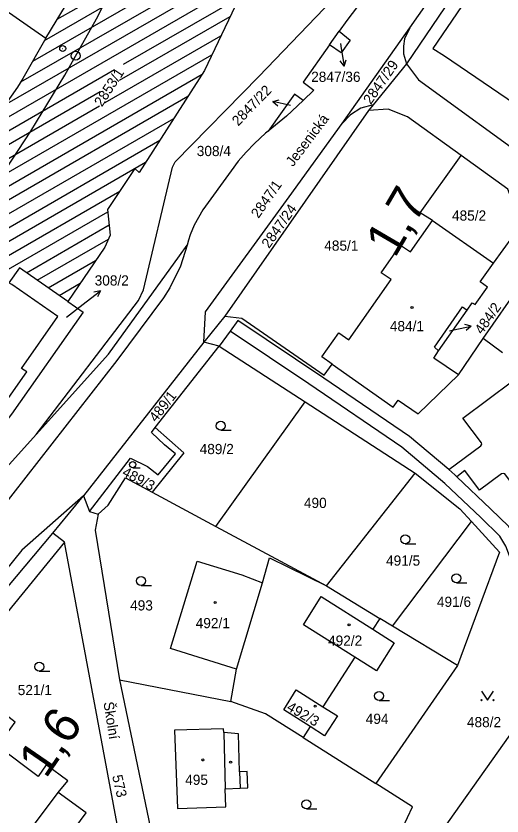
# Model space of a CAD drawing. Extents: x -558500 to -557517, y -1073973 to -1073051.
# Drawn here: x -558087.2 to -558006.2, y -1073436.6 to -1073303.2 of the extents above; entities that cross this region are included whole.
import ezdxf

# ---------------------------------------------------------------- set-up
doc = ezdxf.new("R2010")
doc.units = 0
for name, color, linetype in [('Hranice parcel', 7, 'Continuous'), ('Kolej', 7, 'Continuous'), ('Návěst místo trati', 7, 'Continuous'), ('Parcelní čísla', 7, 'Continuous'), ('Pop  PČ popisy', 7, 'Continuous'), ('Svazek obcí údolí Desné', 7, 'Continuous'), ('Vnitřní kresba', 7, 'Continuous'), ('Značky budov', 7, 'Continuous'), ('Značky kultur', 7, 'Continuous')]:
    doc.layers.add(name, color=color, linetype=linetype)

msp = doc.modelspace()

# ---------------------------------------------------------------- linework, layer by layer
at = {"layer": 'Hranice parcel'}
for p, q in [((-557994.86, -1073270.9), (-558022.09, -1073311.21)), ((-558099.14, -1073295.15), (-558082.18, -1073306.93)), ((-558034.93, -1073308.06), (-558033.31, -1073305.78)), ((-558033.31, -1073305.78), (-558031.49, -1073307.27)), ((-558032.81, -1073321.13), (-558021.55, -1073305.19)), ((-558031.49, -1073307.27), (-558032.97, -1073309.39)), ((-558032.97, -1073309.39), (-558034.93, -1073308.06)), ((-558022.59, -1073309.53), (-558022.09, -1073311.21)), ((-558022.09, -1073311.21), (-558027.65, -1073318.03)), ((-558037.52, -1073315.57), (-558039.34, -1073317.31)), ((-558039.34, -1073317.31), (-558042.1, -1073319.93)), ((-558027.65, -1073318.03), (-558029.72, -1073318.58)), ((-558027.65, -1073318.03), (-558028.41, -1073318.97)), ((-558028.41, -1073318.97), (-558052.39, -1073353.27)), ((-558042.1, -1073319.93), (-558045.13, -1073322.4)), ((-558045.13, -1073322.4), (-558045.59, -1073322.77)), ((-558017.77, -1073337.32), (-558007.59, -1073344.4)), ((-558058.43, -1073340.61), (-558058.64, -1073341.4)), ((-558058.64, -1073341.4), (-558059.76, -1073344.95)), ((-558009.3, -1073357), (-558003.01, -1073347.89)), ((-558055.85, -1073357.6), (-558055.56, -1073352.56)), ((-558016.74, -1073359.04), (-558011.99, -1073352.26)), ((-558052.39, -1073353.27), (-558055.85, -1073357.6)), ((-558051.46, -1073355.75), (-558053.32, -1073358.25)), ((-558055.85, -1073357.6), (-558075.89, -1073383.19)), ((-558053.32, -1073358.25), (-558055.85, -1073357.6)), ((-558013.44, -1073363.06), (-558009.3, -1073357)), ((-558006.08, -1073359.37), (-558009.3, -1073357)), ((-558063.99, -1073371.84), (-558053.32, -1073358.25)), ((-558053.32, -1073358.25), (-558038.99, -1073367.55)), ((-558053.86, -1073388.3), (-558038.99, -1073367.55)), ((-558038.99, -1073367.55), (-558020.67, -1073379.44)), ((-558035.4, -1073398.23), (-558020.67, -1073379.44)), ((-558075.89, -1073383.19), (-558086.19, -1073392.25)), ((-558081, -1073389.4), (-558075.89, -1073383.19)), ((-558075.89, -1073383.19), (-558074.9, -1073385.82)), ((-558064.49, -1073382.58), (-558053.86, -1073388.3)), ((-558074.9, -1073385.82), (-558073.48, -1073386.28)), ((-558024.42, -1073404.91), (-558011.29, -1073387.48)), ((-558053.86, -1073388.3), (-558035.4, -1073398.23)), ((-558116.63, -1073431.7), (-558081, -1073389.4)), ((-558079.07, -1073390.9), (-558081, -1073389.4)), ((-558068.26, -1073448.76), (-558079.07, -1073390.9)), ((-558035.4, -1073398.23), (-558026.52, -1073403.63)), ((-558039.27, -1073404.7), (-558036.29, -1073400)), ((-558036.29, -1073400), (-558027.69, -1073405.45)), ((-558030.69, -1073410.09), (-558039.27, -1073404.7)), ((-558026.52, -1073403.63), (-558027.69, -1073405.45)), ((-558024.42, -1073404.91), (-558026.52, -1073403.63)), ((-558027.69, -1073405.45), (-558024.15, -1073407.69)), ((-558013.61, -1073411.49), (-558024.42, -1073404.91)), ((-558024.15, -1073407.69), (-558027.08, -1073412.36)), ((-558030.69, -1073410.09), (-558036.02, -1073418.35)), ((-558027.08, -1073412.36), (-558030.69, -1073410.09)), ((-558013.61, -1073411.49), (-558027.22, -1073431.17)), ((-558069.9, -1073413.89), (-558063.79, -1073443.12)), ((-558069.9, -1073413.89), (-558051.38, -1073417.49)), ((-558042.56, -1073418.87), (-558040.48, -1073415.56)), ((-558040.48, -1073415.56), (-558036.02, -1073418.35)), ((-558038.16, -1073421.67), (-558042.56, -1073418.87)), ((-558036.02, -1073418.35), (-558033.6, -1073419.86)), ((-558033.6, -1073419.86), (-558035.74, -1073423.21)), ((-558038.16, -1073421.67), (-558039.34, -1073423.5)), ((-558035.74, -1073423.21), (-558038.16, -1073421.67)), ((-558039.34, -1073423.5), (-558027.22, -1073431.17))]:
    msp.add_line(p, q, dxfattribs=at)
for points in [[(-557998.11, -1073217.81), (-557996.7, -1073222.28), (-557998.38, -1073242.39), (-558002.78, -1073257.43), (-558008.62, -1073269.37), (-558024.06, -1073293.44), (-558032.02, -1073303.96), (-558033.31, -1073305.78)], [(-558021.55, -1073305.19), (-558007.79, -1073285.56), (-557998.91, -1073272.25), (-557998.29, -1073271.45), (-557997.41, -1073270.82), (-557995.96, -1073270.7)], [(-557992.18, -1073271.14), (-558017.7, -1073308.66), (-558015.75, -1073309.85), (-558004.08, -1073317.8), (-557996.67, -1073322.48), (-557993.43, -1073325.31), (-557988.49, -1073331.84)], [(-558021.55, -1073305.19), (-558022.41, -1073307.04), (-558022.62, -1073308.24), (-558022.59, -1073309.53)], [(-558034.93, -1073308.06), (-558039.34, -1073314.26), (-558037.52, -1073315.57)], [(-558022.09, -1073311.21), (-558020.08, -1073313.87), (-558000.41, -1073328.2), (-557993.92, -1073334.5), (-557986.04, -1073343.93), (-557967.1, -1073369.2), (-557918.24, -1073434.51), (-557914.64, -1073436.24), (-557909.55, -1073436.22), (-557905.05, -1073434.1), (-557902.57, -1073430.65), (-557891.22, -1073414.37), (-557877.97, -1073395.43)], [(-558039.34, -1073317.31), (-558040.78, -1073316.28), (-558045.13, -1073322.4)], [(-558029.72, -1073318.58), (-558031.41, -1073319.68), (-558032.81, -1073321.13)], [(-558012.98, -1073326.49), (-558021.93, -1073320.01), (-558025.13, -1073318.78), (-558028.41, -1073318.97)], [(-558055.56, -1073352.56), (-558041.67, -1073333.36), (-558032.81, -1073321.13)], [(-558045.59, -1073322.77), (-558047.44, -1073324.48), (-558048.82, -1073325.91), (-558050.13, -1073327.44), (-558051.32, -1073329.04), (-558056.02, -1073335.51), (-558057.5, -1073338.08), (-558058.16, -1073339.69), (-558058.43, -1073340.61)], [(-558017.77, -1073337.32), (-558019.82, -1073336.05), (-558012.98, -1073326.49)], [(-558007.59, -1073344.4), (-558004.4, -1073339.98), (-558003.75, -1073335.95), (-558005.22, -1073332.12), (-558012.98, -1073326.49)], [(-558034.47, -1073361.24), (-558036.19, -1073360.05), (-558033.38, -1073356.04), (-558031.73, -1073357.2), (-558024.67, -1073347.17), (-558026.34, -1073346.01), (-558023.11, -1073341.4), (-558021.44, -1073342.56), (-558017.77, -1073337.32)], [(-558083.8, -1073372.96), (-558071.77, -1073359.59), (-558059.92, -1073343.2), (-558058.64, -1073341.4)], [(-558011.99, -1073352.26), (-558011.14, -1073351.05), (-558010.65, -1073351.33), (-558008.6, -1073348.45), (-558009.82, -1073347.53), (-558007.59, -1073344.4)], [(-558059.76, -1073344.95), (-558061.55, -1073348.53), (-558062.6, -1073350.23), (-558070.37, -1073360.66), (-558089.91, -1073385.65), (-558114.04, -1073415.6), (-558119.93, -1073422.75), (-558120.74, -1073423.38), (-558121.71, -1073423.79), (-558122.74, -1073423.86)], [(-558100.88, -1073366.68), (-558093.95, -1073371.49), (-558091.09, -1073367.38), (-558089.54, -1073368.47), (-558085.38, -1073362.53), (-558086.24, -1073361.96), (-558080.2, -1073353.3), (-558087.87, -1073347.97), (-558088.33, -1073347.7)], [(-558016.74, -1073359.04), (-558017.42, -1073358.44), (-558012.76, -1073351.73), (-558011.99, -1073352.26)], [(-558052.39, -1073353.27), (-558049.55, -1073353.62), (-558035.82, -1073363.11), (-558034.47, -1073361.24)], [(-558015.07, -1073378.83), (-558021.62, -1073373.3), (-558035.88, -1073363.58), (-558050.18, -1073353.97), (-558051.46, -1073355.75)], [(-557997.16, -1073446.28), (-557996.18, -1073446.14), (-557992.37, -1073440.37), (-557993.13, -1073429.99), (-557993.58, -1073428.02), (-558004.25, -1073395), (-558005.55, -1073391.58), (-558006.57, -1073389.94), (-558009.69, -1073386.81), (-558015.69, -1073381.13), (-558022.86, -1073375.1), (-558038.38, -1073364.54), (-558051.46, -1073355.75)], [(-558015.07, -1073378.83), (-558009.7, -1073374.87), (-558009.55, -1073374.62), (-558009.63, -1073374.36), (-558012.72, -1073370.26), (-557996.07, -1073357.8), (-557992.97, -1073361.92), (-557992.74, -1073362.04), (-557992.48, -1073361.98), (-557989.05, -1073359.38), (-557985.61, -1073364.04), (-557988.36, -1073366.15), (-557988.52, -1073366.38), (-557988.48, -1073366.66), (-557985.4, -1073370.76), (-558002.63, -1073383.68), (-558005.71, -1073379.56), (-558005.98, -1073379.48), (-558006.26, -1073379.51), (-558009.96, -1073382.24), (-558012.37, -1073378.99), (-558013.71, -1073380.01)], [(-558013.44, -1073363.06), (-558017.55, -1073360.24), (-558016.74, -1073359.04)], [(-558034.47, -1073361.24), (-558024.32, -1073368.43), (-558023.47, -1073367.24), (-558020.17, -1073369.56), (-558013.44, -1073363.06)], [(-558074.9, -1073385.82), (-558068.06, -1073376.95), (-558065.25, -1073378.32), (-558063.46, -1073379.72), (-558060.6, -1073376.18), (-558062.42, -1073374.7), (-558064.61, -1073372.63), (-558063.99, -1073371.84)], [(-558063.99, -1073371.84), (-558059.19, -1073376.03), (-558064.49, -1073382.58)], [(-558020.67, -1073379.44), (-558013.21, -1073385.39), (-558011.29, -1073387.48)], [(-558013.71, -1073380.01), (-558014.05, -1073379.69), (-558015.07, -1073378.83)], [(-558073.48, -1073386.28), (-558071.82, -1073384.76), (-558068.89, -1073380.22), (-558064.49, -1073382.58)], [(-557986.61, -1073406.29), (-557987.5, -1073406.44), (-558001.47, -1073396.48), (-558002.38, -1073393.7), (-558003.7, -1073390.42), (-558005.05, -1073388.34), (-558008.08, -1073385.35), (-558013.71, -1073380.01)], [(-558073.48, -1073386.28), (-558073.96, -1073388.93), (-558069.9, -1073413.89)], [(-558011.29, -1073387.48), (-558006.6, -1073392.58), (-558013.61, -1073411.49)], [(-558079.07, -1073390.9), (-558096.99, -1073412.88), (-558100.23, -1073417.28)], [(-558086.19, -1073392.25), (-558100.56, -1073410.01), (-558117.51, -1073431.08), (-558131.78, -1073449.27), (-558138.48, -1073457.68), (-558143.38, -1073464.02), (-558146.99, -1073468.89), (-558150.46, -1073473.83), (-558152.02, -1073476.41), (-558154.26, -1073480.97), (-558156.46, -1073486.6), (-558158.91, -1073494.31), (-558160.3, -1073500.48), (-558162.16, -1073510.4), (-558165.76, -1073536.46), (-558169.94, -1073565.43), (-558173.74, -1073591.61), (-558177.66, -1073620.33), (-558178.51, -1073631.87), (-558179.02, -1073643), (-558179.24, -1073655.12), (-558179.45, -1073666.94), (-558179.49, -1073675.4)], [(-558051.38, -1073417.49), (-558050.42, -1073412.09), (-558061.44, -1073408.67), (-558056.95, -1073394.08), (-558049.56, -1073396.36), (-558046.09, -1073397.7), (-558044.91, -1073393.54), (-558035.4, -1073398.23)], [(-558079.09, -1073440.91), (-558075.49, -1073436.06), (-558080.13, -1073432.64), (-558078.53, -1073430.7), (-558082.12, -1073428.01), (-558083.47, -1073429.99), (-558090.26, -1073424.91), (-558087.3, -1073420.92), (-558091.08, -1073418.03), (-558093.98, -1073421.97), (-558100.23, -1073417.28)], [(-558039.34, -1073423.5), (-558045.61, -1073419.54), (-558051.38, -1073417.49)], [(-558049.8, -1073431.93), (-558048.54, -1073431.88), (-558048.64, -1073429.15), (-558049.91, -1073429.2), (-558050.08, -1073422.86), (-558052.56, -1073422.66), (-558052.57, -1073422.02), (-558060.76, -1073422.24), (-558060.26, -1073435.32), (-558052.21, -1073435.02), (-558052.32, -1073432.02), (-558049.8, -1073431.93)], [(-558023.22, -1073448.98), (-558004.82, -1073423.06), (-557993.94, -1073430.83), (-558002.36, -1073442.69), (-558001.05, -1073443.62)], [(-558024.27, -1073448.53), (-558022.77, -1073438.58), (-558021.1, -1073435.02), (-558027.22, -1073431.17)]]:
    msp.add_lwpolyline(points, dxfattribs=at)
at = {"layer": 'Kolej'}
msp.add_lwpolyline([(-558164.78, -1073439.38), (-558155.66, -1073426.13), (-558147.22, -1073413.85), (-558143.69, -1073408.73), (-558141.06, -1073404.9), (-558137.3, -1073399.44), (-558134.57, -1073395.46), (-558131.72, -1073391.31), (-558124.89, -1073381.38), (-558115.4, -1073367.56), (-558106.18, -1073354.16), (-558097.49, -1073341.51), (-558095.26, -1073338.27), (-558090.95, -1073331.93), (-558084.7, -1073322.4), (-558079.04, -1073313.09), (-558073.77, -1073303.7), (-558068.68, -1073293.77)], dxfattribs=at)
at = {"layer": 'Návěst místo trati'}
msp.add_line((-558079.43, -1073308.65), (-558079.33, -1073308.65), dxfattribs=at)
for centre, radius in [((-558079.38, -1073308.65), 0.5), ((-558077.22, -1073309.86), 0.75)]:
    msp.add_circle(centre, radius, dxfattribs=at)
at = {"layer": 'Pop  PČ popisy'}
for p, q in [((-558033.09, -1073307.84), (-558032.96, -1073308.65)), ((-558032.96, -1073308.65), (-558032.49, -1073311.61)), ((-558032.49, -1073311.61), (-558033.14, -1073310.7)), ((-558032.49, -1073311.61), (-558032.15, -1073310.55)), ((-558044.37, -1073317.47), (-558043.29, -1073317.2)), ((-558041.45, -1073318.14), (-558044.37, -1073317.47)), ((-558044.37, -1073317.47), (-558043.51, -1073318.18)), ((-558075.47, -1073350.88), (-558073.1, -1073349.03)), ((-558073.1, -1073349.03), (-558074.2, -1073349.25)), ((-558073.1, -1073349.03), (-558073.59, -1073350.04)), ((-558078.72, -1073353.4), (-558075.47, -1073350.88)), ((-558014.95, -1073355.7), (-558014.23, -1073355.56)), ((-558014.23, -1073355.56), (-558011.3, -1073354.94)), ((-558011.3, -1073354.94), (-558012.38, -1073354.65)), ((-558011.3, -1073354.94), (-558012.17, -1073355.63))]:
    msp.add_line(p, q, dxfattribs=at)
at = {"layer": 'Svazek obcí údolí Desné'}
for p, q in [((-558080.29, -1073303.78), (-558043.65, -1073282.63)), ((-558082.4, -1073307.31), (-558044.27, -1073285.3)), ((-558084.38, -1073310.76), (-558044.89, -1073287.97)), ((-558086.37, -1073314.22), (-558045.51, -1073290.64)), ((-558089.02, -1073318.06), (-558046.97, -1073293.79)), ((-558091.87, -1073322.02), (-558048.48, -1073296.97)), ((-558069.24, -1073311.26), (-558049.99, -1073300.15)), ((-558069.89, -1073313.95), (-558051.5, -1073303.33)), ((-558072.29, -1073317.64), (-558053.01, -1073306.51)), ((-558103.16, -1073337.77), (-558054.52, -1073309.69)), ((-558094.72, -1073325.97), (-558070.74, -1073312.13)), ((-558105.92, -1073341.68), (-558056.17, -1073312.95)), ((-558108.69, -1073345.58), (-558058.52, -1073316.62)), ((-558097.57, -1073329.93), (-558073.14, -1073315.82)), ((-558100.39, -1073333.87), (-558073.26, -1073318.21)), ((-558111.45, -1073349.49), (-558060.87, -1073320.29)), ((-558114.21, -1073353.39), (-558063.22, -1073323.95)), ((-558116.98, -1073357.3), (-558065.57, -1073327.62)), ((-558119.74, -1073361.21), (-558069.87, -1073332.41)), ((-558122.51, -1073365.11), (-558071.87, -1073335.87)), ((-558085.42, -1073346.01), (-558071.63, -1073338.05)), ((-558083.61, -1073347.27), (-558071.76, -1073340.43)), ((-558081.79, -1073348.53), (-558073.89, -1073343.97)), ((-558086.59, -1073345.2), (-558088.33, -1073347.7)), ((-558078.52, -1073350.81), (-558086.59, -1073345.2)), ((-558079.98, -1073349.8), (-558076.46, -1073347.76)), ((-558083.8, -1073372.96), (-558066.74, -1073350.64)), ((-558092.4, -1073382.52), (-558083.8, -1073372.96))]:
    msp.add_line(p, q, dxfattribs=at)
for points in [[(-558082.18, -1073306.93), (-558073.77, -1073292.96), (-558066.53, -1073276.76), (-558060.05, -1073257.85), (-558056.4, -1073244.89), (-558045.6, -1073201.5), (-558043.14, -1073189.96)], [(-558025.67, -1073189.86), (-558032.09, -1073212.63), (-558035.15, -1073249.33), (-558039.97, -1073265.01), (-558041.24, -1073272.26), (-558045.55, -1073290.79), (-558055.77, -1073312.33), (-558066.64, -1073329.29), (-558067.37, -1073328.67), (-558071.91, -1073335.47), (-558071.45, -1073339.78), (-558072.38, -1073341.74), (-558078.52, -1073350.81)], [(-558066.74, -1073350.64), (-558065.9, -1073348.86), (-558061.08, -1073328.44), (-558060.65, -1073327.54), (-558046.7, -1073313.29), (-558030.4, -1073296.27), (-558015.33, -1073274.48), (-558010.02, -1073266.4), (-558006.82, -1073259.79), (-558003.58, -1073251.39), (-558001.93, -1073245.63), (-558000.3, -1073233.47), (-558000.14, -1073230.76), (-558000.21, -1073228.76), (-558000.67, -1073225.31), (-558001.93, -1073222.03), (-558003.18, -1073219.55), (-558003.41, -1073218.32), (-558003.28, -1073217.31), (-558002.8, -1073216.38), (-558000.9, -1073214.81), (-557999.34, -1073213.91), (-558005.3, -1073194.99), (-558007.3, -1073189.81)], [(-558082.18, -1073306.93), (-558086.02, -1073313.63), (-558086.89, -1073315.11), (-558091.21, -1073321.1)], [(-558078.52, -1073350.81), (-558075.97, -1073352.58), (-558087.9, -1073369.62), (-558096.11, -1073380.17)]]:
    msp.add_lwpolyline(points, dxfattribs=at)
at = {"layer": 'Vnitřní kresba'}
for p, q in [((-558050.42, -1073412.09), (-558046.09, -1073397.7)), ((-558052.56, -1073422.66), (-558052.32, -1073432.02)), ((-558049.91, -1073429.2), (-558049.8, -1073431.93)), ((-558086.64, -1073441.31), (-558080.13, -1073432.64))]:
    msp.add_line(p, q, dxfattribs=at)
at = {"layer": 'Značky budov'}
for centre in [(-558021.18, -1073351.82), (-558053.98, -1073400.98), (-558031.67, -1073404.71), (-558037.33, -1073418.27), (-558056.04, -1073427.22), (-558051.4, -1073427.58)]:
    msp.add_circle(centre, 0.175, dxfattribs=at)
at = {"layer": 'Značky kultur'}
for p, q in [((-558053.04, -1073372.28), (-558051.29, -1073372.28)), ((-558067.72, -1073378.52), (-558066.5, -1073378.52)), ((-558022.31, -1073391.2), (-558020.56, -1073391.2)), ((-558066.32, -1073398.13), (-558064.57, -1073398.13)), ((-558013.78, -1073397.68), (-558012.03, -1073397.68)), ((-558083.29, -1073412.44), (-558081.54, -1073412.44)), ((-558026.66, -1073417.3), (-558024.91, -1073417.3)), ((-558038.77, -1073435.36), (-558037.02, -1073435.36))]:
    msp.add_line(p, q, dxfattribs=at)
msp.add_lwpolyline([(-558009.6, -1073415.75), (-558008.6, -1073417.25), (-558007.6, -1073415.75)], dxfattribs=at)
for centre, radius in [((-558053.04, -1073371.53), 0.75), ((-558067.72, -1073378), 0.525), ((-558022.31, -1073390.45), 0.75), ((-558066.32, -1073397.38), 0.75), ((-558013.78, -1073396.93), 0.75), ((-558083.29, -1073411.69), 0.75), ((-558026.66, -1073416.55), 0.75), ((-558009.6, -1073417.25), 0.1), ((-558007.6, -1073417.25), 0.1), ((-558038.77, -1073434.61), 0.75)]:
    msp.add_circle(centre, radius, dxfattribs=at)

# ---------------------------------------------------------------- texts
at = {"layer": 'Návěst místo trati'}
for s, rotation, p in [('1,7', 59.7051, (-558024.05, -1073343.72)), ('1,6', 55.5139, (-558082.19, -1073430.47))]:
    msp.add_text(s, height=6, rotation=rotation, dxfattribs=at).set_placement(p)
at = {"layer": 'Parcelní čísla'}
for s, rotation, p in [('2847/29', 55, (-558028.06, -1073318.09)), ('2853/1', 57, (-558072.84, -1073318.48)), ('2847/22', 46, (-558050.14, -1073321.67)), ('2847/1', 55, (-558046.76, -1073337.06)), ('2847/24', 55, (-558045, -1073342.08)), ('484/2', 55, (-558009.5, -1073356.42)), ('489/1', 52, (-558063.81, -1073371.04)), ('489/3', 332, (-558069.62, -1073379.77)), ('492/3', 330, (-558042.19, -1073418.87)), ('573', 283, (-558071.15, -1073429.91))]:
    msp.add_text(s, height=1.7, rotation=rotation, dxfattribs=at).set_placement(p)
for s, p in [('2847/36', (-558037.98, -1073314.21)), ('308/4', (-558057.04, -1073326.58)), ('485/2', (-558014.52, -1073337.34)), ('485/1', (-558035.8, -1073342.35)), ('308/2', (-558074.05, -1073348.15)), ('484/1', (-558024.87, -1073355.77)), ('489/2', (-558056.56, -1073376.25)), ('490', (-558039.19, -1073385.23)), ('491/5', (-558025.51, -1073394.84)), ('493', (-558068.15, -1073402.31)), ('491/6', (-558017.03, -1073401.71)), ('492/1', (-558057.22, -1073405.26)), ('492/2', (-558035.17, -1073408.19)), ('521/1', (-558086.87, -1073416.42)), ('494', (-558028.89, -1073421.21)), ('488/2', (-558012.03, -1073421.76)), ('495', (-558058.97, -1073431.38))]:
    msp.add_text(s, height=1.7, dxfattribs=at).set_placement(p)
at = {"layer": 'Pop  PČ popisy'}
for s, rotation, p in [('Jesenická', 53, (-558041.01, -1073328.46)), ('Školní', 279, (-558072.59, -1073417.65))]:
    msp.add_text(s, height=1.7, rotation=rotation, dxfattribs=at).set_placement(p)

doc.saveas('drawing.dxf')
